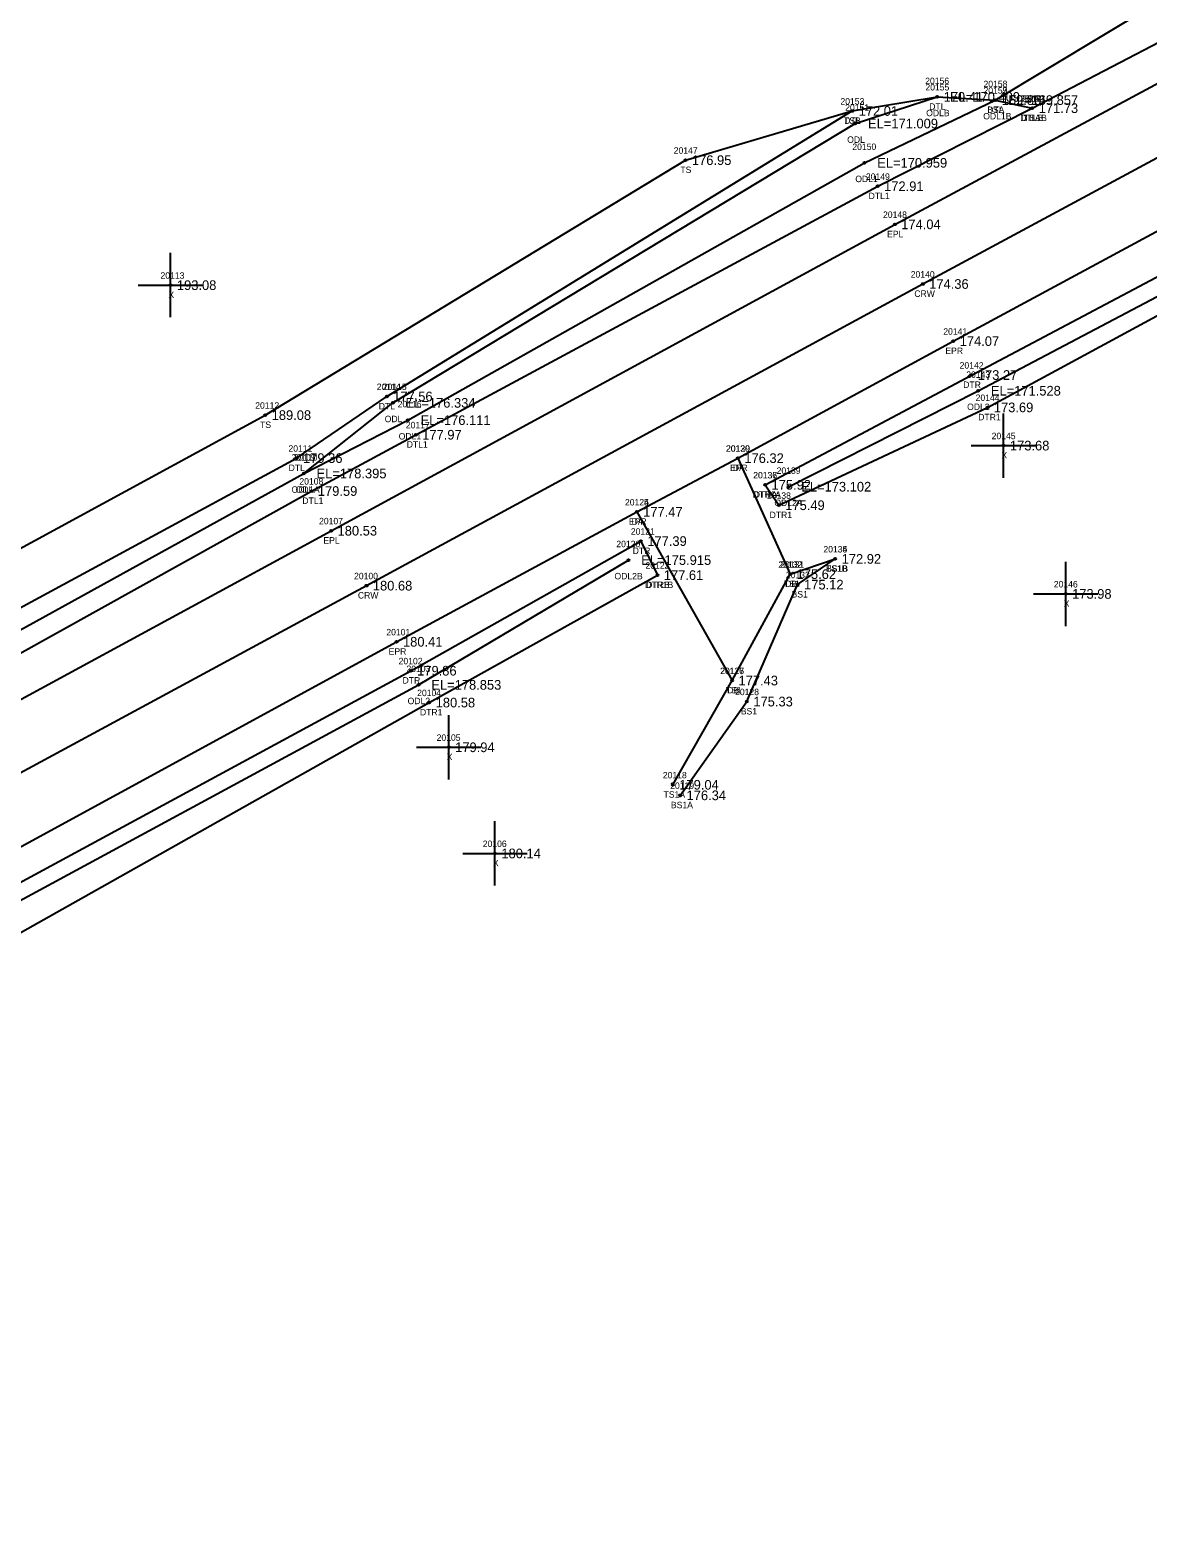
# Model space of a CAD drawing. Extents: x 2279528 to 2280976, y 1061373 to 1062235.
# Drawn here: x 2279762.5 to 2279936.3, y 1061423.7 to 1061658.1 of the extents above; entities that cross this region are included whole.
import ezdxf

# ---------------------------------------------------------------- set-up
doc = ezdxf.new("R2010")
doc.units = 0
for name, color, linetype in [('RD_DTM_BkLn1', 7, 'Continuous'), ('RD_DTM_BkLn2', 7, 'Continuous'), ('RD_DTM_BkLn_txCode', 7, 'Continuous'), ('RD_EX_Driveway', 7, 'Continuous'), ('RD_EX_Driveway_txCode', 7, 'Continuous'), ('RD_EX_H2O', 7, 'Continuous'), ('RD_EX_H2O_txCode', 7, 'Continuous'), ('RD_EX_Misc', 7, 'Continuous'), ('RD_EX_Misc_txCode', 7, 'Continuous'), ('RD_EX_Road', 7, 'Continuous'), ('RD_EX_Road_txCode', 7, 'Continuous'), ('RD_EX_TX_Driveway_ELEV', 7, 'Continuous'), ('RD_EX_TX_H2O_ELEV', 7, 'Continuous'), ('RD_EX_TX_Misc_ELEV', 7, 'Continuous'), ('RD_EX_TX_Road_ELEV', 7, 'Continuous'), ('RD_HC_Survey_ELEV', 7, 'Continuous'), ('RD_HC_Survey_txCode', 7, 'Continuous'), ('RD_SMD_Locator', 7, 'Continuous')]:
    doc.layers.add(name, color=color, linetype=linetype)

msp = doc.modelspace()

# ---------------------------------------------------------------- linework, layer by layer
at = {"layer": 'RD_DTM_BkLn1'}
msp.add_lwpolyline([(2279559.79, 1061433.13), (2279641.23, 1061477.49), (2279727.93, 1061524.84), (2279814.76, 1061571.75), (2279901.26, 1061618.64), (2279982.8, 1061662.56), (2280064.7, 1061706.86), (2280148.08, 1061751.86), (2280234.22, 1061798.46), (2280310.96, 1061840.01), (2280397.69, 1061887.57), (2280487.27, 1061936.5), (2280573.03, 1061983.12), (2280654.64, 1062027.66), (2280741.28, 1062074.45), (2280833.39, 1062123.87), (2280892.52, 1062155.9), (2280939.46, 1062181.85)], dxfattribs=at)
at = {"layer": 'RD_DTM_BkLn2'}
for points in [[(2279912.54, 1061647.23), (2279971.15, 1061682.49), (2280052.17, 1061728.33), (2280132.75, 1061780.82), (2280164.61, 1061792.77), (2280185.62, 1061809.36)], [(2279918.28, 1061645.97), (2279973.97, 1061675.02), (2280055.41, 1061723.24), (2280139.04, 1061770.27), (2280166.79, 1061783.8), (2280197.35, 1061795.14), (2280211.16, 1061800.79)], [(2279708.88, 1061539.55), (2279712.68, 1061551.32), (2279799.03, 1061598.26), (2279864.37, 1061637.89), (2279890.29, 1061645.53)], [(2279862.41, 1061540.8), (2279871.61, 1061557), (2279880.64, 1061573.54), (2279887.65, 1061575.91)], [(2279863.54, 1061539.16), (2279873.92, 1061553.73), (2279881.81, 1061571.91), (2279887.65, 1061575.91)]]:
    msp.add_lwpolyline(points, dxfattribs=at)
at = {"layer": 'RD_EX_Driveway'}
for p, q in [((2279872.52, 1061591.57), (2279880.64, 1061573.54)), ((2279856.79, 1061583.22), (2279871.61, 1061557))]:
    msp.add_line(p, q, dxfattribs=at)
at = {"layer": 'RD_EX_H2O'}
for points in [[(2279876.74, 1061587.42), (2279908.82, 1061604.49), (2279990.5, 1061647.75), (2280059.22, 1061681.62), (2280066.92, 1061680.28)], [(2279876.74, 1061587.42), (2279878.88, 1061584.25), (2279911.31, 1061599.46), (2279992.1, 1061643.19), (2280062.36, 1061676.46), (2280066.92, 1061680.28)], [(2279880.37, 1061587.13), (2279909.85, 1061602.05), (2279991.4, 1061644.97), (2280061.63, 1061677.82), (2280066.92, 1061680.28)], [(2279678.26, 1061523.4), (2279708.88, 1061539.55), (2279716.91, 1061544.53), (2279803.91, 1061591.58), (2279817.92, 1061601.16), (2279890.29, 1061645.53), (2279903.5, 1061647.72), (2279912.54, 1061647.23), (2279918.28, 1061645.97)], [(2279678.26, 1061523.4), (2279681.28, 1061517.73), (2279720.3, 1061538.66), (2279806.21, 1061586.46), (2279822.44, 1061595.21), (2279894.25, 1061633.83), (2279918.28, 1061645.97)], [(2279682.32, 1061522.01), (2279718.73, 1061541.61), (2279805.01, 1061589.19), (2279818.85, 1061600.16), (2279890.75, 1061643.58), (2279903.5, 1061647.72)], [(2279805.01, 1061589.19), (2279821.19, 1061597.47), (2279892.18, 1061637.47), (2279912.54, 1061647.23)], [(2279715.99, 1061501.35), (2279734.56, 1061511.38), (2279821.65, 1061558.53), (2279857.43, 1061578.68), (2279860, 1061573.39)], [(2279718.96, 1061499.94), (2279735.82, 1061509.25), (2279822.86, 1061556.33), (2279855.49, 1061575.73)], [(2279715.99, 1061501.35), (2279718.69, 1061495.17), (2279737.88, 1061504.81), (2279824.53, 1061553.58), (2279860, 1061573.39)]]:
    msp.add_lwpolyline(points, dxfattribs=at)
at = {"layer": 'RD_EX_Misc'}
for p, q in [((2279784.3, 1061613.46), (2279784.3, 1061623.46)), ((2279779.3, 1061618.46), (2279789.3, 1061618.46)), ((2279913.81, 1061588.52), (2279913.81, 1061598.52)), ((2279908.81, 1061593.52), (2279918.81, 1061593.52)), ((2279923.48, 1061565.47), (2279923.48, 1061575.47)), ((2279918.48, 1061570.47), (2279928.48, 1061570.47)), ((2279827.56, 1061541.63), (2279827.56, 1061551.63)), ((2279822.56, 1061546.63), (2279832.56, 1061546.63)), ((2279834.75, 1061525.13), (2279834.75, 1061535.13)), ((2279829.75, 1061530.13), (2279839.75, 1061530.13))]:
    msp.add_line(p, q, dxfattribs=at)
at = {"layer": 'RD_EX_Road'}
for points in [[(2279554.31, 1061441.46), (2279636.61, 1061486.51), (2279673.46, 1061506.76), (2279683.06, 1061512.21), (2279723.14, 1061533.54), (2279809.28, 1061580.29), (2279896.91, 1061627.91), (2279977.07, 1061671.02), (2280059.64, 1061715.57), (2280142.91, 1061760.72), (2280228.83, 1061807.06), (2280306.04, 1061849.18), (2280392.98, 1061896.71), (2280482.82, 1061945.75), (2280567.83, 1061991.78), (2280649.94, 1062036.55), (2280660.56, 1062042.19), (2280676.12, 1062050.66), (2280737.28, 1062083.64), (2280828.54, 1062132.77), (2280887.86, 1062164.61), (2280934.91, 1062190.9)], [(2279563.73, 1061423.75), (2279645.81, 1061468.43), (2279687.22, 1061491.24), (2279716.07, 1061507.1), (2279732.53, 1061515.67), (2279819.45, 1061563.03), (2279856.79, 1061583.22), (2279872.52, 1061591.57), (2279906, 1061609.76), (2279987.33, 1061653.65)]]:
    msp.add_lwpolyline(points, dxfattribs=at)
at = {"layer": 'RD_SMD_Locator'}
for centre in [(2279903.5, 1061647.72), (2279903.5, 1061647.72), (2279912.54, 1061647.23), (2279912.54, 1061647.23), (2279912.54, 1061647.23), (2279918.28, 1061645.97), (2279918.28, 1061645.97), (2279918.28, 1061645.97), (2279890.29, 1061645.53), (2279890.29, 1061645.53), (2279890.75, 1061643.58), (2279864.37, 1061637.89), (2279892.18, 1061637.47), (2279894.25, 1061633.83), (2279896.91, 1061627.91), (2279784.3, 1061618.46), (2279901.26, 1061618.64), (2279906, 1061609.76), (2279908.82, 1061604.49), (2279817.92, 1061601.16), (2279909.85, 1061602.05), (2279818.85, 1061600.16), (2279911.31, 1061599.46), (2279799.03, 1061598.26), (2279821.19, 1061597.47), (2279822.44, 1061595.21), (2279913.81, 1061593.52), (2279803.91, 1061591.58), (2279872.52, 1061591.57), (2279872.52, 1061591.57), (2279805.01, 1061589.19), (2279805.01, 1061589.19), (2279876.74, 1061587.42), (2279876.74, 1061587.42), (2279880.37, 1061587.13), (2279806.21, 1061586.46), (2279856.79, 1061583.22), (2279856.79, 1061583.22), (2279878.88, 1061584.25), (2279809.28, 1061580.29), (2279857.43, 1061578.68), (2279855.49, 1061575.73), (2279887.65, 1061575.91), (2279887.65, 1061575.91), (2279860, 1061573.39), (2279860, 1061573.39), (2279880.64, 1061573.54), (2279880.64, 1061573.54), (2279814.76, 1061571.75), (2279881.81, 1061571.91), (2279923.48, 1061570.47), (2279819.45, 1061563.03), (2279821.65, 1061558.53), (2279871.61, 1061557), (2279871.61, 1061557), (2279822.86, 1061556.33), (2279824.53, 1061553.58), (2279873.92, 1061553.73), (2279827.56, 1061546.63), (2279862.41, 1061540.8), (2279863.54, 1061539.16), (2279834.75, 1061530.13)]:
    msp.add_circle(centre, 0.15, dxfattribs=at)

# ---------------------------------------------------------------- texts
at = {"layer": 'RD_DTM_BkLn_txCode'}
for s, p in [('20159', (2279910.7, 1061648.23)), ('20152', (2279888.46, 1061646.53)), ('BSA', (2279911.27, 1061645.23)), ('20162', (2279916.42, 1061646.97)), ('TSB', (2279889.03, 1061643.53)), ('TSA', (2279917, 1061643.97)), ('20147', (2279862.54, 1061638.89)), ('TS', (2279863.58, 1061635.89)), ('20112', (2279797.48, 1061599.26)), ('TS', (2279798.24, 1061596.26)), ('20134', (2279885.81, 1061576.91)), ('20135', (2279885.81, 1061576.91)), ('20131', (2279879.09, 1061574.54)), ('20133', (2279879.97, 1061572.91)), ('TS1B', (2279886.21, 1061573.91)), ('BS1B', (2279886.23, 1061573.91)), ('TS1', (2279879.68, 1061571.54)), ('BS1', (2279880.86, 1061569.91)), ('20126', (2279869.75, 1061558)), ('TS1', (2279870.65, 1061555)), ('20128', (2279872.08, 1061554.73)), ('BS1', (2279872.97, 1061551.73)), ('20118', (2279860.85, 1061541.8)), ('20119', (2279861.99, 1061540.16)), ('TS1A', (2279860.96, 1061538.8)), ('BS1A', (2279862.11, 1061537.16))]:
    msp.add_text(s, height=1, dxfattribs=at).set_placement(p)
at = {"layer": 'RD_EX_Driveway_txCode'}
for s, p in [('20130', (2279870.65, 1061592.57)), ('DA', (2279871.73, 1061589.57)), ('20125', (2279854.96, 1061584.22)), ('DA', (2279856, 1061581.22)), ('20132', (2279878.81, 1061574.54)), ('DB', (2279879.86, 1061571.54)), ('20127', (2279869.78, 1061558)), ('DB', (2279870.83, 1061555))]:
    msp.add_text(s, height=1, dxfattribs=at).set_placement(p)
at = {"layer": 'RD_EX_H2O_txCode'}
for s, p in [('20156', (2279901.64, 1061649.72)), ('20155', (2279901.67, 1061648.72)), ('20158', (2279910.7, 1061649.23)), ('20157', (2279910.7, 1061648.23)), ('20153', (2279888.46, 1061646.53)), ('20151', (2279889.2, 1061645.58)), ('DTL', (2279902.26, 1061645.72)), ('DTL', (2279911.3, 1061645.23)), ('20160', (2279916.38, 1061646.97)), ('20161', (2279916.71, 1061646.97)), ('DTL', (2279889.05, 1061643.53)), ('ODLB', (2279901.79, 1061644.72)), ('ODL1B', (2279910.66, 1061644.23)), ('DTL1B', (2279916.4, 1061643.97)), ('DTLB', (2279916.57, 1061643.97)), ('ODL', (2279889.51, 1061640.58)), ('20150', (2279890.31, 1061639.47)), ('ODL1', (2279890.77, 1061634.47)), ('20149', (2279892.42, 1061634.83)), ('DTL1', (2279892.84, 1061631.83)), ('20142', (2279906.99, 1061605.49)), ('20143', (2279908.02, 1061604.05)), ('20114', (2279816.37, 1061602.16)), ('20115', (2279817.3, 1061602.16)), ('DTR', (2279907.55, 1061602.49)), ('20144', (2279909.48, 1061600.46)), ('DTL', (2279816.68, 1061599.16)), ('20116', (2279819.62, 1061599.47)), ('ODL2', (2279908.16, 1061599.05)), ('ODL', (2279817.61, 1061597.16)), ('20117', (2279820.89, 1061596.21)), ('DTR1', (2279909.88, 1061597.46)), ('ODL1', (2279819.78, 1061594.47)), ('20111', (2279802.64, 1061592.58)), ('20109', (2279803.14, 1061591.19)), ('20110', (2279803.42, 1061591.19)), ('DTL1', (2279821.03, 1061593.21)), ('DTL', (2279802.67, 1061589.58)), ('20139', (2279878.54, 1061589.13)), ('20108', (2279804.34, 1061587.46)), ('20136', (2279874.89, 1061588.42)), ('20137', (2279874.91, 1061588.42)), ('ODL1A', (2279803.11, 1061586.19)), ('ODL', (2279803.77, 1061586.19)), ('DTL1', (2279804.8, 1061584.46)), ('DTR1A', (2279874.82, 1061585.42)), ('DTRA', (2279874.99, 1061585.42)), ('20138', (2279877.04, 1061585.25)), ('ODL2A', (2279878.19, 1061584.13)), ('DTR1', (2279877.45, 1061582.25)), ('20121', (2279855.88, 1061579.68)), ('20120', (2279853.62, 1061577.73)), ('DTR', (2279856.16, 1061576.68)), ('ODL2B', (2279853.33, 1061572.73)), ('20122', (2279858.16, 1061574.39)), ('20123', (2279858.16, 1061574.39)), ('DTR1B', (2279858.09, 1061571.39)), ('DTRB', (2279858.26, 1061571.39)), ('20102', (2279819.77, 1061559.53)), ('20103', (2279820.99, 1061558.33)), ('DTR', (2279820.38, 1061556.53)), ('20104', (2279822.65, 1061554.58)), ('ODL2', (2279821.17, 1061553.33)), ('DTR1', (2279823.09, 1061551.58))]:
    msp.add_text(s, height=1, dxfattribs=at).set_placement(p)
at = {"layer": 'RD_EX_Misc_txCode'}
for s, p in [('20113', (2279782.75, 1061619.46)), ('X', (2279783.98, 1061616.46)), ('20145', (2279911.97, 1061594.52)), ('X', (2279913.49, 1061591.52)), ('20146', (2279921.63, 1061571.47)), ('X', (2279923.17, 1061568.47)), ('20105', (2279825.68, 1061547.63)), ('X', (2279827.24, 1061544.63)), ('20106', (2279832.85, 1061531.13)), ('X', (2279834.43, 1061528.13))]:
    msp.add_text(s, height=1, dxfattribs=at).set_placement(p)
at = {"layer": 'RD_EX_Road_txCode'}
for s, p in [('20148', (2279895.08, 1061628.91)), ('EPL', (2279895.71, 1061625.91)), ('20141', (2279904.45, 1061610.76)), ('EPR', (2279904.77, 1061607.76)), ('20129', (2279870.69, 1061592.57)), ('EPR', (2279871.29, 1061589.57)), ('20124', (2279854.96, 1061584.22)), ('20107', (2279807.4, 1061581.29)), ('EPR', (2279855.57, 1061581.22)), ('EPL', (2279808.07, 1061578.29)), ('20101', (2279817.86, 1061564.03)), ('EPR', (2279818.22, 1061561.03))]:
    msp.add_text(s, height=1, dxfattribs=at).set_placement(p)
at = {"layer": 'RD_EX_TX_Driveway_ELEV'}
for s, p in [('176.32', (2279873.52, 1061590.82)), ('177.47', (2279857.79, 1061582.47)), ('175.62', (2279881.64, 1061572.79)), ('177.43', (2279872.61, 1061556.25))]:
    msp.add_text(s, height=1.5, dxfattribs=at).set_placement(p)
at = {"layer": 'RD_EX_TX_H2O_ELEV'}
for s, p in [('170.41', (2279904.5, 1061646.97)), ('EL=170.409', (2279905.5, 1061646.97)), ('172.01', (2279891.29, 1061644.78)), ('169.86', (2279913.54, 1061646.48)), ('EL=169.857', (2279914.54, 1061646.48)), ('171.73', (2279919.28, 1061645.22)), ('171.73', (2279919.28, 1061645.22)), ('EL=171.009', (2279892.75, 1061642.83)), ('EL=170.959', (2279894.18, 1061636.72)), ('172.91', (2279895.25, 1061633.08)), ('173.27', (2279909.82, 1061603.74)), ('177.56', (2279818.92, 1061600.41)), ('EL=171.528', (2279911.85, 1061601.3)), ('EL=176.334', (2279820.85, 1061599.41)), ('173.69', (2279912.31, 1061598.71)), ('EL=176.111', (2279823.19, 1061596.72)), ('177.97', (2279823.44, 1061594.46)), ('179.36', (2279804.91, 1061590.83)), ('EL=178.395', (2279807.01, 1061588.44)), ('EL=178.395', (2279807.01, 1061588.44)), ('179.59', (2279807.21, 1061585.71)), ('175.92', (2279877.74, 1061586.67)), ('175.92', (2279877.74, 1061586.67)), ('EL=173.102', (2279882.37, 1061586.38)), ('175.49', (2279879.88, 1061583.5)), ('177.39', (2279858.43, 1061577.93)), ('EL=175.915', (2279857.49, 1061574.98)), ('177.61', (2279861, 1061572.64)), ('177.61', (2279861, 1061572.64)), ('179.86', (2279822.65, 1061557.78)), ('EL=178.853', (2279824.86, 1061555.58)), ('180.58', (2279825.53, 1061552.83))]:
    msp.add_text(s, height=1.5, dxfattribs=at).set_placement(p)
at = {"layer": 'RD_EX_TX_Misc_ELEV'}
for s, p in [('172.01', (2279891.29, 1061644.78)), ('169.86', (2279913.54, 1061646.48)), ('171.73', (2279919.28, 1061645.22)), ('176.95', (2279865.37, 1061637.14)), ('193.08', (2279785.3, 1061617.71)), ('189.08', (2279800.03, 1061597.51)), ('173.68', (2279914.81, 1061592.77)), ('172.92', (2279888.65, 1061575.16)), ('172.92', (2279888.65, 1061575.16)), ('175.62', (2279881.64, 1061572.79)), ('175.12', (2279882.81, 1061571.16)), ('173.98', (2279924.48, 1061569.72)), ('177.43', (2279872.61, 1061556.25)), ('175.33', (2279874.92, 1061552.98)), ('179.94', (2279828.56, 1061545.88)), ('179.04', (2279863.41, 1061540.05)), ('176.34', (2279864.54, 1061538.41)), ('180.14', (2279835.75, 1061529.38))]:
    msp.add_text(s, height=1.5, dxfattribs=at).set_placement(p)
at = {"layer": 'RD_EX_TX_Road_ELEV'}
for s, p in [('174.04', (2279897.91, 1061627.16)), ('174.07', (2279907, 1061609.01)), ('176.32', (2279873.52, 1061590.82)), ('177.47', (2279857.79, 1061582.47)), ('180.53', (2279810.28, 1061579.54)), ('180.41', (2279820.45, 1061562.28))]:
    msp.add_text(s, height=1.5, dxfattribs=at).set_placement(p)
at = {"layer": 'RD_HC_Survey_ELEV'}
for s, p in [('174.36', (2279902.26, 1061617.89)), ('180.68', (2279815.76, 1061571))]:
    msp.add_text(s, height=1.5, dxfattribs=at).set_placement(p)
at = {"layer": 'RD_HC_Survey_txCode'}
for s, p in [('20140', (2279899.39, 1061619.64)), ('CRW', (2279899.95, 1061616.64)), ('20100', (2279812.84, 1061572.75)), ('CRW', (2279813.44, 1061569.75))]:
    msp.add_text(s, height=1, dxfattribs=at).set_placement(p)

doc.saveas('drawing.dxf')
